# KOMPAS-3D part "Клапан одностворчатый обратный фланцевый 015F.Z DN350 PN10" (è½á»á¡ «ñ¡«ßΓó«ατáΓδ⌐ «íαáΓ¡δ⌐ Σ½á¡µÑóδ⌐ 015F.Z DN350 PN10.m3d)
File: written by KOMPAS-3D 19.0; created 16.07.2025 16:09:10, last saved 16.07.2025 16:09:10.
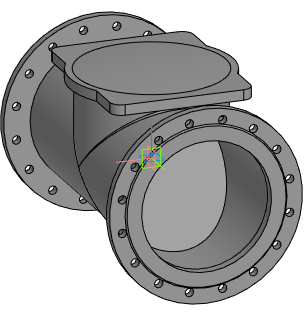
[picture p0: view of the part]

Document properties: Полное имя файла: E:\Dendor Работа Сачек\3D для проектировщиков\5.4 Тип 015F.Z. Клапан одностворчатый обратный фланцевый\stp_Клапан одностворчатый обратный фланцевый 015F.Z PN10_16\Клапан одностворчатый обратный фланцевый 015F.Z DN350 PN10.m3d

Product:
- Part/product: Клапан одностворчатый обратный фланцевый 015F.Z DN350 PN10

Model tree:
1. Операция без истории:1  (labels: Клапан одностворчатый обратный фланцевый 015F.Z DN350 PN10)
2. Операция без истории:2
